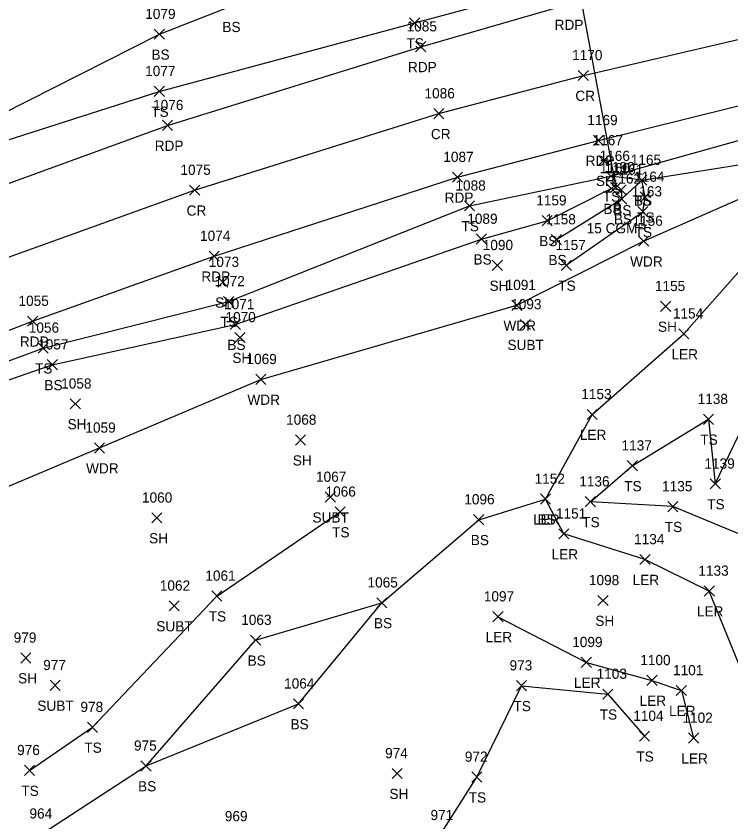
# Model space of a CAD drawing. Extents: x 1586965 to 1590952, y 716317 to 720029.
# Drawn here: x 1587502.3 to 1587642.6, y 719678.7 to 719836.9 of the extents above; entities that cross this region are included whole.
import ezdxf

# ---------------------------------------------------------------- set-up
doc = ezdxf.new("R2010")
doc.units = 0
for name, color, linetype in [('D_A', 7, 'Continuous'), ('D_C', 7, 'Continuous'), ('D_I', 7, 'Continuous'), ('D_TIC', 7, 'Continuous'), ('DCP', 7, 'Continuous'), ('L_A', 7, 'Continuous'), ('L_I', 7, 'Continuous'), ('L_TIC', 7, 'Continuous'), ('LARO', 7, 'Continuous'), ('LAWA', 7, 'Continuous'), ('LELB', 7, 'Continuous'), ('P_A', 7, 'Continuous'), ('P_I', 7, 'Continuous'), ('P_TIC', 7, 'Continuous'), ('PET', 7, 'Continuous'), ('PRC', 7, 'Continuous'), ('U_A', 7, 'Continuous'), ('U_I', 7, 'Continuous'), ('U_TIC', 7, 'Continuous')]:
    doc.layers.add(name, color=color, linetype=linetype)

msp = doc.modelspace()

# ---------------------------------------------------------------- linework, layer by layer
at = {"layer": 'D_TIC'}
for points in [[(1587619.04, 719802.24), (1587621.04, 719804.24)], [(1587621.04, 719802.24), (1587619.04, 719804.24)]]:
    msp.add_lwpolyline(points, dxfattribs=at)
at = {"layer": 'DCP'}
msp.add_lwpolyline([(1587610.43, 719855.04), (1587620.04, 719803.24)], dxfattribs=at)
at = {"layer": 'L_TIC'}
for points in [[(1587579.58, 719834.52), (1587581.58, 719836.52)], [(1587581.58, 719834.52), (1587579.58, 719836.52)], [(1587529.46, 719832.31), (1587531.46, 719834.31)], [(1587531.46, 719832.31), (1587529.46, 719834.31)], [(1587529.45, 719821.09), (1587531.45, 719823.09)], [(1587531.45, 719821.09), (1587529.45, 719823.09)], [(1587616.67, 719807.52), (1587618.67, 719809.52)], [(1587618.67, 719807.52), (1587616.67, 719809.52)], [(1587618.1, 719804.45), (1587620.1, 719806.45)], [(1587620.1, 719804.45), (1587618.1, 719806.45)], [(1587618.1, 719804.45), (1587620.1, 719806.45)], [(1587620.1, 719804.45), (1587618.1, 719806.45)], [(1587624.17, 719803.67), (1587626.17, 719805.67)], [(1587626.17, 719803.67), (1587624.17, 719805.67)], [(1587624.17, 719803.67), (1587626.17, 719805.67)], [(1587626.17, 719803.67), (1587624.17, 719805.67)], [(1587618.17, 719802.04), (1587620.17, 719804.04)], [(1587620.17, 719802.04), (1587618.17, 719804.04)], [(1587620.11, 719801.76), (1587622.11, 719803.76)], [(1587622.11, 719801.76), (1587620.11, 719803.76)], [(1587624.83, 719800.35), (1587626.83, 719802.35)], [(1587626.83, 719800.35), (1587624.83, 719802.35)], [(1587620.24, 719799.99), (1587622.24, 719801.99)], [(1587622.24, 719799.99), (1587620.24, 719801.99)], [(1587620.24, 719799.99), (1587622.24, 719801.99)], [(1587622.24, 719799.99), (1587620.24, 719801.99)], [(1587590.35, 719798.64), (1587592.35, 719800.64)], [(1587592.35, 719798.64), (1587590.35, 719800.64)], [(1587624.36, 719797.48), (1587626.36, 719799.48)], [(1587626.36, 719797.48), (1587624.36, 719799.48)], [(1587605.58, 719795.72), (1587607.58, 719797.72)], [(1587607.58, 719795.72), (1587605.58, 719797.72)], [(1587592.67, 719792.11), (1587594.67, 719794.11)], [(1587594.67, 719792.11), (1587592.67, 719794.11)], [(1587607.39, 719792), (1587609.39, 719794)], [(1587609.39, 719792), (1587607.39, 719794)], [(1587624.51, 719791.71), (1587626.51, 719793.71)], [(1587626.51, 719791.71), (1587624.51, 719793.71)], [(1587595.8, 719786.95), (1587597.8, 719788.95)], [(1587597.8, 719786.95), (1587595.8, 719788.95)], [(1587609.34, 719786.96), (1587611.34, 719788.96)], [(1587611.34, 719786.96), (1587609.34, 719788.96)], [(1587541.93, 719783.65), (1587543.93, 719785.65)], [(1587543.93, 719783.65), (1587541.93, 719785.65)], [(1587543.05, 719779.86), (1587545.05, 719781.86)], [(1587545.05, 719779.86), (1587543.05, 719781.86)], [(1587599.64, 719779.12), (1587601.64, 719781.12)], [(1587601.64, 719779.12), (1587599.64, 719781.12)], [(1587628.86, 719778.91), (1587630.86, 719780.91)], [(1587630.86, 719778.91), (1587628.86, 719780.91)], [(1587544.37, 719775.35), (1587546.37, 719777.35)], [(1587546.37, 719775.35), (1587544.37, 719777.35)], [(1587632.4, 719773.52), (1587634.4, 719775.52)], [(1587634.4, 719773.52), (1587632.4, 719775.52)], [(1587545.3, 719772.8), (1587547.3, 719774.8)], [(1587547.3, 719772.8), (1587545.3, 719774.8)], [(1587506.65, 719770.73), (1587508.65, 719772.73)], [(1587508.65, 719770.73), (1587506.65, 719772.73)], [(1587508.44, 719767.45), (1587510.44, 719769.45)], [(1587510.44, 719767.45), (1587508.44, 719769.45)], [(1587549.39, 719764.58), (1587551.39, 719766.58)], [(1587551.39, 719764.58), (1587549.39, 719766.58)], [(1587512.96, 719759.78), (1587514.96, 719761.78)], [(1587514.96, 719759.78), (1587512.96, 719761.78)], [(1587614.41, 719757.7), (1587616.41, 719759.7)], [(1587616.41, 719757.7), (1587614.41, 719759.7)], [(1587637.24, 719756.75), (1587639.24, 719758.75)], [(1587639.24, 719756.75), (1587637.24, 719758.75)], [(1587557.16, 719752.68), (1587559.16, 719754.68)], [(1587559.16, 719752.68), (1587557.16, 719754.68)], [(1587517.72, 719751.12), (1587519.72, 719753.12)], [(1587519.72, 719751.12), (1587517.72, 719753.12)], [(1587622.3, 719747.63), (1587624.3, 719749.63)], [(1587624.3, 719747.63), (1587622.3, 719749.63)], [(1587638.59, 719744.07), (1587640.59, 719746.07)], [(1587640.59, 719744.07), (1587638.59, 719746.07)], [(1587605.25, 719741.09), (1587607.25, 719743.09)], [(1587607.25, 719741.09), (1587605.25, 719743.09)], [(1587605.25, 719741.09), (1587607.25, 719743.09)], [(1587607.25, 719741.09), (1587605.25, 719743.09)], [(1587614.07, 719740.57), (1587616.07, 719742.57)], [(1587616.07, 719740.57), (1587614.07, 719742.57)], [(1587630.26, 719739.62), (1587632.26, 719741.62)], [(1587632.26, 719739.62), (1587630.26, 719741.62)], [(1587528.96, 719737.4), (1587530.96, 719739.4)], [(1587530.96, 719737.4), (1587528.96, 719739.4)], [(1587564.96, 719738.57), (1587566.96, 719740.57)], [(1587566.96, 719738.57), (1587564.96, 719740.57)], [(1587592.15, 719737.05), (1587594.15, 719739.05)], [(1587594.15, 719737.05), (1587592.15, 719739.05)], [(1587608.87, 719734.27), (1587610.87, 719736.27)], [(1587610.87, 719734.27), (1587608.87, 719736.27)], [(1587624.78, 719729.23), (1587626.78, 719731.23)], [(1587626.78, 719729.23), (1587624.78, 719731.23)], [(1587637.4, 719723.05), (1587639.4, 719725.05)], [(1587639.4, 719723.05), (1587637.4, 719725.05)], [(1587540.74, 719722.07), (1587542.74, 719724.07)], [(1587542.74, 719722.07), (1587540.74, 719724.07)], [(1587573.14, 719720.74), (1587575.14, 719722.74)], [(1587575.14, 719720.74), (1587573.14, 719722.74)], [(1587573.14, 719720.74), (1587575.14, 719722.74)], [(1587575.14, 719720.74), (1587573.14, 719722.74)], [(1587616.55, 719721.2), (1587618.55, 719723.2)], [(1587618.55, 719721.2), (1587616.55, 719723.2)], [(1587595.93, 719718.01), (1587597.93, 719720.01)], [(1587597.93, 719718.01), (1587595.93, 719720.01)], [(1587548.35, 719713.4), (1587550.35, 719715.4)], [(1587550.35, 719713.4), (1587548.35, 719715.4)], [(1587503.24, 719709.92), (1587505.24, 719711.92)], [(1587505.24, 719709.92), (1587503.24, 719711.92)], [(1587613.28, 719709.05), (1587615.28, 719711.05)], [(1587615.28, 719709.05), (1587613.28, 719711.05)], [(1587626.15, 719705.51), (1587628.15, 719707.51)], [(1587628.15, 719705.51), (1587626.15, 719707.51)], [(1587600.56, 719704.47), (1587602.56, 719706.47)], [(1587602.56, 719704.47), (1587600.56, 719706.47)], [(1587617.49, 719702.82), (1587619.49, 719704.82)], [(1587619.49, 719702.82), (1587617.49, 719704.82)], [(1587631.93, 719703.52), (1587633.93, 719705.52)], [(1587633.93, 719703.52), (1587631.93, 719705.52)], [(1587556.77, 719700.91), (1587558.77, 719702.91)], [(1587558.77, 719700.91), (1587556.77, 719702.91)], [(1587516.33, 719696.31), (1587518.33, 719698.31)], [(1587518.33, 719696.31), (1587516.33, 719698.31)], [(1587624.69, 719694.57), (1587626.69, 719696.57)], [(1587626.69, 719694.57), (1587624.69, 719696.57)], [(1587634.34, 719694.19), (1587636.34, 719696.19)], [(1587636.34, 719694.19), (1587634.34, 719696.19)], [(1587526.84, 719688.73), (1587528.84, 719690.73)], [(1587528.84, 719688.73), (1587526.84, 719690.73)], [(1587526.84, 719688.73), (1587528.84, 719690.73)], [(1587528.84, 719688.73), (1587526.84, 719690.73)], [(1587503.96, 719687.85), (1587505.96, 719689.85)], [(1587505.96, 719687.85), (1587503.96, 719689.85)], [(1587576.13, 719687.24), (1587578.13, 719689.24)], [(1587578.13, 719687.24), (1587576.13, 719689.24)], [(1587591.78, 719686.55), (1587593.78, 719688.55)], [(1587593.78, 719686.55), (1587591.78, 719688.55)]]:
    msp.add_lwpolyline(points, dxfattribs=at)
at = {"layer": 'LARO'}
for points in [[(1587647.76, 719701.07), (1587638.4, 719724.05), (1587625.78, 719730.23), (1587609.87, 719735.27), (1587606.25, 719742.09), (1587615.41, 719758.7), (1587633.4, 719774.52), (1587656.59, 719800.68)], [(1587596.93, 719719.01), (1587614.28, 719710.05), (1587627.15, 719706.51), (1587632.93, 719704.52), (1587635.34, 719695.19)]]:
    msp.add_lwpolyline(points, dxfattribs=at)
at = {"layer": 'LAWA'}
msp.add_lwpolyline([(1587401.27, 719626.51), (1587435.01, 719634.6), (1587448.14, 719647.08), (1587470.91, 719665.01), (1587461.04, 719696.06), (1587450.54, 719719.33), (1587487.07, 719738.78), (1587518.72, 719752.12), (1587550.39, 719765.58), (1587600.64, 719780.12), (1587625.51, 719792.71), (1587653.44, 719805), (1587664.38, 719814.47), (1587690.31, 719819.83), (1587699.11, 719820.97), (1587725.45, 719821.57), (1587738.15, 719822.66), (1587747.89, 719823.3), (1587771.26, 719823.5), (1587792.66, 719819.32), (1587813.67, 719812.11)], dxfattribs=at)
at = {"layer": 'LELB'}
for points in [[(1587348.34, 719750.32), (1587376.14, 719764.57), (1587411.23, 719784.15), (1587458.35, 719804.18), (1587473.61, 719812.83), (1587489.06, 719812.38), (1587530.46, 719833.31), (1587544.39, 719838.73), (1587578.28, 719845.78), (1587610.35, 719855.43), (1587636.65, 719869.8), (1587651.78, 719871.98), (1587673.75, 719879.3), (1587684.98, 719885.25), (1587696.5, 719901.07), (1587712.21, 719917.3), (1587727.23, 719932.21), (1587743.8, 719944.38), (1587761.72, 719949.74)], [(1587348.34, 719750.32), (1587376.14, 719764.57), (1587411.23, 719784.15), (1587458.35, 719804.18), (1587473.61, 719812.83), (1587489.06, 719812.38), (1587530.46, 719833.31), (1587544.39, 719838.73), (1587578.28, 719845.78), (1587610.35, 719855.43), (1587636.65, 719869.8), (1587651.78, 719871.98), (1587673.75, 719879.3), (1587684.98, 719885.25), (1587696.5, 719901.07), (1587712.21, 719917.3), (1587727.23, 719932.21), (1587743.8, 719944.38), (1587761.72, 719949.74)], [(1587377.37, 719757.84), (1587414.05, 719779.22), (1587461.92, 719797.99), (1587490.32, 719809.23), (1587530.45, 719822.09), (1587580.58, 719835.52), (1587609.69, 719843.39), (1587653.83, 719853.5), (1587683.02, 719862.16), (1587697.57, 719874.31), (1587709.76, 719884.81), (1587725.71, 719899.33), (1587733.52, 719907.93), (1587757.13, 719931.09), (1587771.49, 719945.87)], [(1587377.37, 719757.84), (1587414.05, 719779.22), (1587461.92, 719797.99), (1587490.32, 719809.23), (1587530.45, 719822.09), (1587580.58, 719835.52), (1587609.69, 719843.39), (1587653.83, 719853.5), (1587683.02, 719862.16), (1587697.57, 719874.31), (1587709.76, 719884.81), (1587725.71, 719899.33), (1587733.52, 719907.93), (1587757.13, 719931.09), (1587771.49, 719945.87)], [(1587398.24, 719722.21), (1587438.94, 719742.74), (1587477.78, 719760.7), (1587507.65, 719771.73), (1587544.05, 719780.86), (1587591.35, 719799.64), (1587619.1, 719805.45), (1587663.03, 719817.76), (1587689.98, 719823.61), (1587724.39, 719827.01), (1587769.54, 719828.25), (1587817.81, 719818.92)], [(1587398.24, 719722.21), (1587438.94, 719742.74), (1587477.78, 719760.7), (1587507.65, 719771.73), (1587544.05, 719780.86), (1587591.35, 719799.64), (1587619.1, 719805.45), (1587663.03, 719817.76), (1587689.98, 719823.61), (1587724.39, 719827.01), (1587769.54, 719828.25), (1587817.81, 719818.92)], [(1587651.83, 719700.97), (1587648.01, 719733.7), (1587631.26, 719740.62), (1587615.07, 719741.57), (1587623.3, 719748.63), (1587638.24, 719757.75), (1587639.59, 719745.07), (1587645.2, 719756.74), (1587652.38, 719771.7), (1587661.64, 719782.87), (1587675.63, 719789.54), (1587687.83, 719800.98), (1587693.68, 719811.37), (1587702.61, 719814.76), (1587716.08, 719806.7), (1587717.74, 719791.78), (1587733.84, 719775.17), (1587724.64, 719762.06), (1587727.41, 719748.69)], [(1587651.83, 719700.97), (1587648.01, 719733.7), (1587631.26, 719740.62), (1587615.07, 719741.57), (1587623.3, 719748.63), (1587638.24, 719757.75), (1587639.59, 719745.07), (1587645.2, 719756.74), (1587652.38, 719771.7), (1587661.64, 719782.87), (1587675.63, 719789.54), (1587687.83, 719800.98), (1587693.68, 719811.37), (1587702.61, 719814.76), (1587716.08, 719806.7), (1587717.74, 719791.78), (1587733.84, 719775.17), (1587724.64, 719762.06), (1587727.41, 719748.69)], [(1587400.93, 719718.94), (1587441.36, 719738.52), (1587479.32, 719758.06), (1587509.44, 719768.45), (1587545.37, 719776.35), (1587593.67, 719793.11), (1587606.58, 719796.72), (1587619.17, 719803.04), (1587621.11, 719802.76), (1587621.24, 719800.99), (1587625.17, 719804.67), (1587651.6, 719808.85)], [(1587400.93, 719718.94), (1587441.36, 719738.52), (1587479.32, 719758.06), (1587509.44, 719768.45), (1587545.37, 719776.35), (1587593.67, 719793.11), (1587606.58, 719796.72), (1587619.17, 719803.04), (1587621.11, 719802.76), (1587621.24, 719800.99), (1587625.17, 719804.67), (1587651.6, 719808.85)], [(1587610.34, 719787.96), (1587625.36, 719798.48), (1587625.83, 719801.35), (1587625.17, 719804.67), (1587619.1, 719805.45)], [(1587610.34, 719787.96), (1587625.36, 719798.48), (1587625.83, 719801.35), (1587625.17, 719804.67), (1587619.1, 719805.45)], [(1587608.39, 719793), (1587621.24, 719800.99)], [(1587608.39, 719793), (1587621.24, 719800.99)], [(1587423.24, 719608.06), (1587427.23, 719597.73), (1587440.34, 719603.55), (1587448.78, 719605.67), (1587462.07, 719611.33), (1587473.34, 719623.95), (1587472.46, 719637.71), (1587475.67, 719655.32), (1587507.38, 719676.4), (1587527.84, 719689.73), (1587549.35, 719714.4), (1587574.14, 719721.74), (1587593.15, 719738.05), (1587606.25, 719742.09)], [(1587423.24, 719608.06), (1587427.23, 719597.73), (1587440.34, 719603.55), (1587448.78, 719605.67), (1587462.07, 719611.33), (1587473.34, 719623.95), (1587472.46, 719637.71), (1587475.67, 719655.32), (1587507.38, 719676.4), (1587527.84, 719689.73), (1587549.35, 719714.4), (1587574.14, 719721.74), (1587593.15, 719738.05), (1587606.25, 719742.09)], [(1587504.96, 719688.85), (1587517.33, 719697.31), (1587541.74, 719723.07), (1587565.96, 719739.57)], [(1587504.96, 719688.85), (1587517.33, 719697.31), (1587541.74, 719723.07), (1587565.96, 719739.57)], [(1587527.84, 719689.73), (1587557.77, 719701.91), (1587574.14, 719721.74)], [(1587527.84, 719689.73), (1587557.77, 719701.91), (1587574.14, 719721.74)], [(1587512.91, 719650.53), (1587526, 719660.31), (1587534.24, 719668.41), (1587545.73, 719675.88), (1587564.18, 719673.61), (1587585.49, 719676.1), (1587592.78, 719687.55), (1587601.56, 719705.47), (1587618.49, 719703.82), (1587625.69, 719695.57)], [(1587512.91, 719650.53), (1587526, 719660.31), (1587534.24, 719668.41), (1587545.73, 719675.88), (1587564.18, 719673.61), (1587585.49, 719676.1), (1587592.78, 719687.55), (1587601.56, 719705.47), (1587618.49, 719703.82), (1587625.69, 719695.57)]]:
    msp.add_lwpolyline(points, dxfattribs=at)
at = {"layer": 'P_TIC'}
for points in [[(1587580.77, 719829.86), (1587582.77, 719831.86)], [(1587582.77, 719829.86), (1587580.77, 719831.86)], [(1587612.69, 719824.22), (1587614.69, 719826.22)], [(1587614.69, 719824.22), (1587612.69, 719826.22)], [(1587584.33, 719816.72), (1587586.33, 719818.72)], [(1587586.33, 719816.72), (1587584.33, 719818.72)], [(1587531.06, 719814.42), (1587533.06, 719816.42)], [(1587533.06, 719814.42), (1587531.06, 719816.42)], [(1587615.65, 719811.47), (1587617.65, 719813.47)], [(1587617.65, 719811.47), (1587615.65, 719813.47)], [(1587587.97, 719804.25), (1587589.97, 719806.25)], [(1587589.97, 719804.25), (1587587.97, 719806.25)], [(1587536.38, 719801.71), (1587538.38, 719803.71)], [(1587538.38, 719801.71), (1587536.38, 719803.71)], [(1587540.23, 719788.76), (1587542.23, 719790.76)], [(1587542.23, 719788.76), (1587540.23, 719790.76)], [(1587504.58, 719776), (1587506.58, 719778)], [(1587506.58, 719776), (1587504.58, 719778)]]:
    msp.add_lwpolyline(points, dxfattribs=at)
at = {"layer": 'PET'}
for points in [[(1587380.68, 719751.95), (1587418.28, 719771.56), (1587465.09, 719790.26), (1587493.56, 719801.4), (1587532.06, 719815.42), (1587581.77, 719830.86), (1587610.56, 719839.15), (1587655.26, 719849.11), (1587685.91, 719854.02), (1587717.2, 719859.97), (1587741.36, 719862.44), (1587760.59, 719863.49), (1587776.56, 719860.57), (1587795.98, 719858.74), (1587820.3, 719853.13)], [(1587395.82, 719726.18), (1587435.88, 719747.89), (1587475.69, 719765.52), (1587505.58, 719777), (1587541.23, 719789.76), (1587588.97, 719805.25), (1587616.65, 719812.47), (1587661.21, 719823.51), (1587689.19, 719828.4), (1587723.88, 719833.21), (1587769.59, 719834.05), (1587819.16, 719826.14)]]:
    msp.add_lwpolyline(points, dxfattribs=at)
at = {"layer": 'PRC'}
msp.add_lwpolyline([(1587388.91, 719738.13), (1587428.57, 719759.37), (1587470.76, 719777.76), (1587498.92, 719788.92), (1587537.38, 719802.71), (1587585.33, 719817.72), (1587613.69, 719825.22), (1587658.7, 719835.7), (1587687.69, 719841.3), (1587721.6, 719845.66), (1587770.57, 719846.88), (1587822.37, 719838.71)], dxfattribs=at)
msp.add_lwpolyline([(1587388.91, 719738.13), (1587428.57, 719759.37), (1587470.76, 719777.76), (1587498.92, 719788.92), (1587537.38, 719802.71), (1587585.33, 719817.72), (1587613.69, 719825.22), (1587658.7, 719835.7), (1587687.69, 719841.3), (1587721.6, 719845.66), (1587770.57, 719846.88), (1587822.37, 719838.71)], dxfattribs=at)
at = {"layer": 'U_TIC'}
for points in [[(1587601.29, 719775.34), (1587603.29, 719777.34)], [(1587603.29, 719775.34), (1587601.29, 719777.34)], [(1587563.02, 719741.48), (1587565.02, 719743.48)], [(1587565.02, 719741.48), (1587563.02, 719743.48)], [(1587532.37, 719720.13), (1587534.37, 719722.13)], [(1587534.37, 719720.13), (1587532.37, 719722.13)], [(1587509.02, 719704.54), (1587511.02, 719706.54)], [(1587511.02, 719704.54), (1587509.02, 719706.54)]]:
    msp.add_lwpolyline(points, dxfattribs=at)

# ---------------------------------------------------------------- texts
at = {"layer": 'D_A'}
msp.add_text('P', height=2, dxfattribs=at).set_placement((1587619.42, 719798.24))
at = {"layer": 'D_C'}
msp.add_text('15 CGMP', height=2, dxfattribs=at).set_placement((1587614.34, 719794.24))
at = {"layer": 'D_I'}
msp.add_text('1190', height=2, dxfattribs=at).set_placement((1587617.83, 719806.24))
at = {"layer": 'L_A'}
for s, p in [('BS', (1587542.83, 719833.73)), ('TS', (1587578.98, 719830.52)), ('BS', (1587528.91, 719828.31)), ('TS', (1587528.86, 719817.09)), ('SH', (1587616.16, 719803.52)), ('TS', (1587617.51, 719800.45)), ('TS', (1587617.51, 719800.45)), ('TS', (1587623.58, 719799.67)), ('BS', (1587623.62, 719799.67)), ('BS', (1587617.62, 719798.04)), ('BS', (1587619.55, 719797.76)), ('BS', (1587619.69, 719795.99)), ('BS', (1587619.69, 719795.99)), ('TS', (1587624.24, 719796.35)), ('TS', (1587589.76, 719794.64)), ('TS', (1587623.77, 719793.48)), ('BS', (1587605.02, 719791.72)), ('BS', (1587592.12, 719788.11)), ('BS', (1587606.83, 719788)), ('WDR', (1587622.87, 719787.71)), ('SH', (1587595.28, 719782.95)), ('TS', (1587608.75, 719782.96)), ('SH', (1587541.42, 719779.65)), ('TS', (1587542.46, 719775.86)), ('WDR', (1587598, 719775.12)), ('SH', (1587628.34, 719774.91)), ('BS', (1587543.81, 719771.35)), ('SH', (1587544.79, 719768.8)), ('LER', (1587630.98, 719769.52)), ('TS', (1587506.06, 719766.73)), ('BS', (1587507.89, 719763.45)), ('WDR', (1587547.75, 719760.58)), ('SH', (1587512.45, 719755.78)), ('LER', (1587612.99, 719753.7)), ('TS', (1587636.65, 719752.75)), ('SH', (1587556.65, 719748.68)), ('WDR', (1587516.08, 719747.12)), ('TS', (1587621.71, 719743.63)), ('TS', (1587638, 719740.07)), ('LER', (1587603.83, 719737.09)), ('BS', (1587604.69, 719737.09)), ('TS', (1587613.48, 719736.57)), ('TS', (1587629.67, 719735.62)), ('TS', (1587564.37, 719734.57)), ('SH', (1587528.45, 719733.4)), ('BS', (1587591.59, 719733.05)), ('LER', (1587607.45, 719730.27)), ('LER', (1587623.36, 719725.23)), ('TS', (1587540.15, 719718.07)), ('LER', (1587635.98, 719719.05)), ('BS', (1587572.58, 719716.74)), ('BS', (1587572.58, 719716.74)), ('SH', (1587616.04, 719717.2)), ('LER', (1587594.51, 719714.01)), ('BS', (1587547.79, 719709.4)), ('SH', (1587502.73, 719705.92)), ('LER', (1587611.86, 719705.05)), ('LER', (1587624.73, 719701.51)), ('TS', (1587599.97, 719700.47)), ('LER', (1587630.51, 719699.52)), ('TS', (1587616.9, 719698.82)), ('BS', (1587556.21, 719696.91)), ('TS', (1587515.74, 719692.31)), ('TS', (1587624.1, 719690.57)), ('LER', (1587632.93, 719690.19)), ('TS', (1587503.37, 719683.85)), ('BS', (1587526.28, 719684.73)), ('BS', (1587526.28, 719684.73)), ('SH', (1587575.62, 719683.24)), ('TS', (1587591.19, 719682.55))]:
    msp.add_text(s, height=2, dxfattribs=at).set_placement(p)
at = {"layer": 'L_I'}
for s, p in [('1079', (1587527.69, 719836.31)), ('1077', (1587527.67, 719825.09)), ('1167', (1587615.5, 719811.52)), ('1166', (1587616.88, 719808.45)), ('1166', (1587616.88, 719808.45)), ('1165', (1587623, 719807.67)), ('1165', (1587623, 719807.67)), ('1160', (1587616.91, 719806.04)), ('1161', (1587619.5, 719805.76)), ('1162', (1587619.07, 719803.99)), ('1162', (1587619.07, 719803.99)), ('1164', (1587623.66, 719804.35)), ('1088', (1587588.58, 719802.64)), ('1163', (1587623.18, 719801.48)), ('1159', (1587604.44, 719799.72)), ('1089', (1587590.9, 719796.11)), ('1158', (1587606.26, 719796)), ('1156', (1587623.33, 719795.71)), ('1090', (1587593.94, 719790.95)), ('1157', (1587608.22, 719790.96)), ('1073', (1587540.16, 719787.65)), ('1072', (1587541.28, 719783.86)), ('1091', (1587598.43, 719783.12)), ('1155', (1587627.73, 719782.91)), ('1071', (1587543.17, 719779.35)), ('1070', (1587543.44, 719776.8)), ('1154', (1587631.27, 719777.52)), ('1056', (1587504.83, 719774.73)), ('1057', (1587506.67, 719771.45)), ('1069', (1587547.56, 719768.58)), ('1058', (1587511.19, 719763.78)), ('1153', (1587613.28, 719761.7)), ('1138', (1587636.12, 719760.75)), ('1068', (1587555.34, 719756.68)), ('1059', (1587515.94, 719755.12)), ('1137', (1587621.18, 719751.63)), ('1139', (1587637.46, 719748.07)), ('1152', (1587604.12, 719745.09)), ('1152', (1587604.12, 719745.09)), ('1136', (1587612.89, 719744.57)), ('1135', (1587629.14, 719743.62)), ('1066', (1587563.08, 719742.57)), ('1060', (1587527.05, 719741.4)), ('1096', (1587590.32, 719741.05)), ('1151', (1587608.31, 719738.27)), ('1134', (1587623.65, 719733.23)), ('1061', (1587539.49, 719726.07)), ('1133', (1587636.27, 719727.05)), ('1065', (1587571.32, 719724.74)), ('1065', (1587571.32, 719724.74)), ('1098', (1587614.78, 719725.2)), ('1097', (1587594.15, 719722.01)), ('1063', (1587546.53, 719717.4)), ('979', (1587501.87, 719713.92)), ('1099', (1587611.5, 719713.05)), ('1100', (1587624.86, 719709.51)), ('973', (1587599.2, 719708.47)), ('1101', (1587631.29, 719707.52)), ('1103', (1587616.29, 719706.82)), ('1064', (1587554.95, 719704.91)), ('978', (1587514.97, 719700.31)), ('1104', (1587623.49, 719698.57)), ('1102', (1587633.14, 719698.19)), ('976', (1587502.54, 719691.85)), ('975', (1587525.48, 719692.73)), ('975', (1587525.48, 719692.73)), ('974', (1587574.77, 719691.24)), ('972', (1587590.42, 719690.55)), ('964', (1587504.97, 719679.4)), ('969', (1587543.31, 719678.88)), ('971', (1587583.69, 719679.1))]:
    msp.add_text(s, height=2, dxfattribs=at).set_placement(p)
at = {"layer": 'P_A'}
for s, p in [('RDP', (1587608.05, 719834.15)), ('RDP', (1587579.26, 719825.86)), ('CR', (1587612.12, 719820.22)), ('CR', (1587583.77, 719812.72)), ('RDP', (1587529.55, 719810.42)), ('RDP', (1587614.14, 719807.47)), ('RDP', (1587586.46, 719800.25)), ('CR', (1587535.81, 719797.71)), ('RDP', (1587538.71, 719784.76)), ('RDP', (1587503.07, 719772))]:
    msp.add_text(s, height=2, dxfattribs=at).set_placement(p)
at = {"layer": 'P_I'}
for s, p in [('1085', (1587579, 719833.86)), ('1170', (1587611.48, 719828.22)), ('1086', (1587582.51, 719820.72)), ('1076', (1587529.23, 719818.42)), ('1169', (1587614.47, 719815.47)), ('1087', (1587586.2, 719808.25)), ('1075', (1587534.6, 719805.71)), ('1074', (1587538.45, 719792.76)), ('1055', (1587502.81, 719780))]:
    msp.add_text(s, height=2, dxfattribs=at).set_placement(p)
at = {"layer": 'U_A'}
for p in [(1587598.79, 719771.34), (1587560.52, 719737.48), (1587529.86, 719716.13), (1587506.51, 719700.54)]:
    msp.add_text('SUBT', height=2, dxfattribs=at).set_placement(p)
at = {"layer": 'U_I'}
for s, p in [('1093', (1587599.52, 719779.34)), ('1067', (1587561.21, 719745.48)), ('1062', (1587530.55, 719724.13)), ('977', (1587507.66, 719708.54))]:
    msp.add_text(s, height=2, dxfattribs=at).set_placement(p)

doc.saveas('drawing.dxf')
